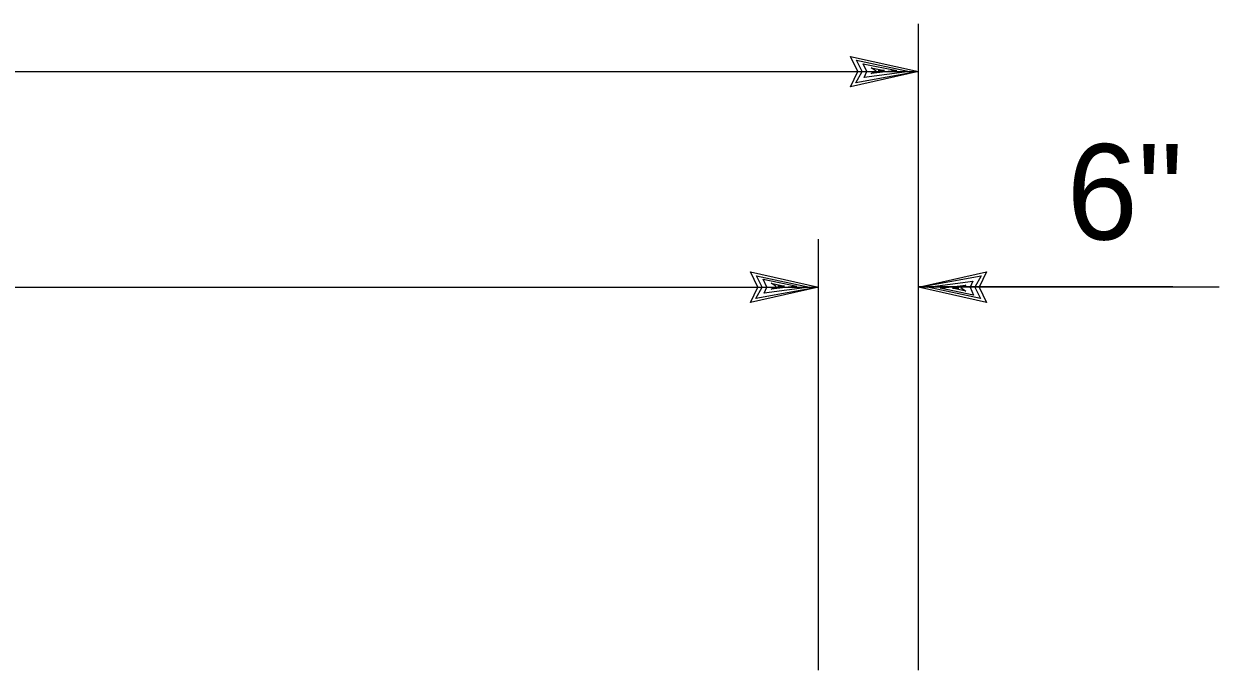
# Model space of a CAD drawing. Extents: x -0.08 to 2.83, y -0.03 to 1.92.
# Drawn here: x 0.9299 to 1.0928, y 1.5885 to 1.6767 of the extents above; entities that cross this region are included whole.
import ezdxf

# ---------------------------------------------------------------- set-up
doc = ezdxf.new("R2010")
doc.units = 0
doc.layers.add('55', color=7, linetype='Continuous')
doc.layers.add('57', color=7, linetype='Continuous')

msp = doc.modelspace()

# ---------------------------------------------------------------- linework, layer by layer
at = {"layer": '55'}
for p, q in [((1.05185, 1.58851), (1.05185, 1.67667)), ((1.04358, 1.67016), (1.04257, 1.67224)), ((1.04257, 1.67224), (1.05185, 1.67016)), ((1.04419, 1.67016), (1.04338, 1.6717)), ((1.04338, 1.6717), (1.05063, 1.67016)), ((1.04479, 1.67016), (1.04432, 1.67123)), ((1.04432, 1.67123), (1.04889, 1.67029)), ((1.04606, 1.67022), (1.04539, 1.67069)), ((1.04539, 1.67069), (1.04721, 1.67029)), ((0.72312, 1.67014), (1.05185, 1.67016)), ((1.05185, 1.67016), (1.04257, 1.66808)), ((1.04257, 1.66808), (1.04358, 1.67016)), ((1.05185, 1.67016), (1.04331, 1.66861)), ((1.04331, 1.66861), (1.04419, 1.67016)), ((1.05063, 1.67016), (1.04445, 1.66935)), ((1.04445, 1.66935), (1.04479, 1.67016)), ((1.04889, 1.67029), (1.04539, 1.66988)), ((1.04539, 1.66988), (1.04606, 1.67022)), ((1.04721, 1.67029), (1.04634, 1.67029)), ((1.03822, 1.58851), (1.03821, 1.64732)), ((1.02994, 1.64075), (1.02893, 1.64284)), ((1.02893, 1.64284), (1.03821, 1.64075)), ((1.03055, 1.64075), (1.02974, 1.6423)), ((1.02974, 1.6423), (1.037, 1.64075)), ((1.03115, 1.64075), (1.03068, 1.64183)), ((1.03068, 1.64183), (1.03525, 1.64089)), ((1.03243, 1.64082), (1.03176, 1.64129)), ((1.03176, 1.64129), (1.03357, 1.64089)), ((1.05185, 1.64077), (1.06112, 1.64285)), ((1.05185, 1.64077), (1.06038, 1.6423)), ((1.05306, 1.64077), (1.05924, 1.64157)), ((1.05924, 1.64157), (1.05891, 1.64077)), ((1.06038, 1.6423), (1.05951, 1.64077)), ((1.06112, 1.64285), (1.06011, 1.64077)), ((0.73644, 1.64074), (1.03821, 1.64075)), ((1.03821, 1.64075), (1.02893, 1.63867)), ((1.02893, 1.63867), (1.02994, 1.64075)), ((1.03821, 1.64075), (1.02967, 1.63921)), ((1.02967, 1.63921), (1.03055, 1.64075)), ((1.037, 1.64075), (1.03081, 1.63995)), ((1.03081, 1.63995), (1.03115, 1.64075)), ((1.03525, 1.64089), (1.03176, 1.64048)), ((1.03176, 1.64048), (1.03243, 1.64082)), ((1.03357, 1.64089), (1.03269, 1.64089)), ((1.08651, 1.64079), (1.05185, 1.64079)), ((1.06112, 1.63868), (1.05185, 1.64077)), ((1.09284, 1.64077), (1.05185, 1.64077)), ((1.06031, 1.63922), (1.05306, 1.64077)), ((1.05481, 1.64062), (1.0583, 1.64103)), ((1.05937, 1.63968), (1.05481, 1.64062)), ((1.0583, 1.64022), (1.05649, 1.64062)), ((1.05649, 1.64062), (1.05736, 1.64062)), ((1.0583, 1.64103), (1.05763, 1.64069)), ((1.05763, 1.64069), (1.0583, 1.64022)), ((1.05891, 1.64077), (1.05937, 1.63968)), ((1.05951, 1.64077), (1.06031, 1.63922)), ((1.06011, 1.64077), (1.06112, 1.63868))]:
    msp.add_line(p, q, dxfattribs=at)

# ---------------------------------------------------------------- texts
at = {"layer": '57'}
msp.add_text('6"', height=0.013021, rotation=0.0033, dxfattribs=at).set_placement((1.07207, 1.64725))

doc.saveas('drawing.dxf')
